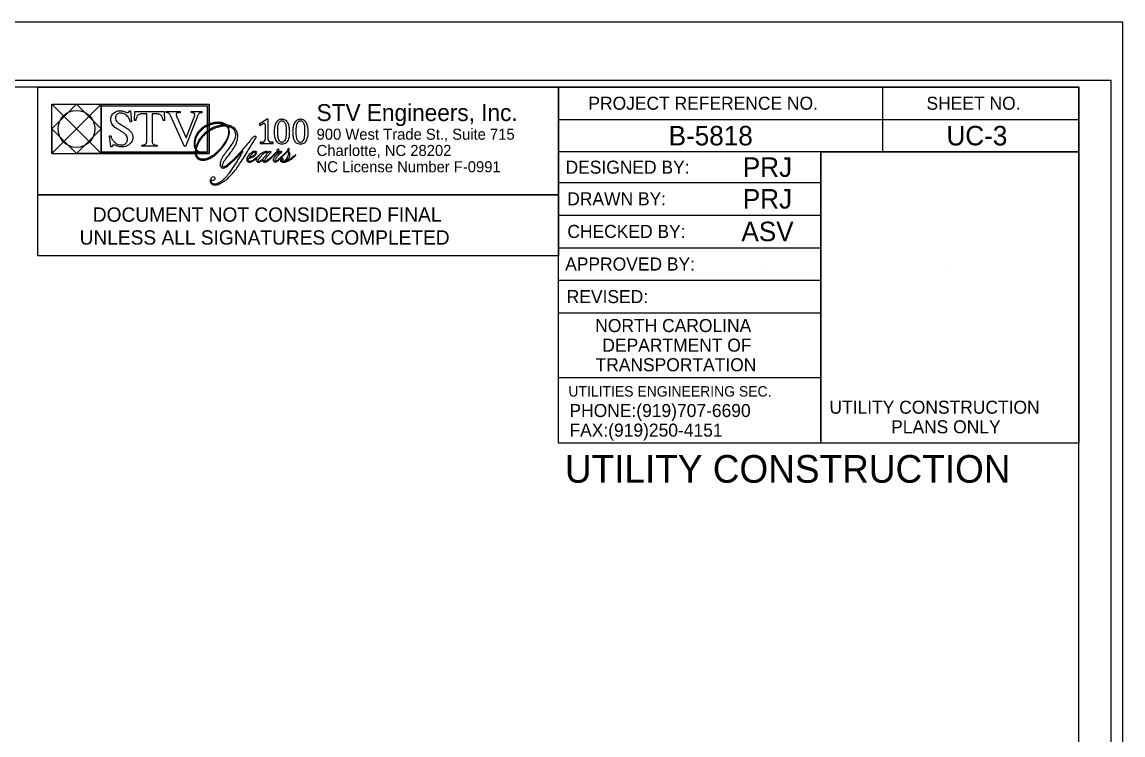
# Model space of a CAD drawing. Extents: x 0 to 674, y 0 to 440.
# Drawn here: x 504.3 to 673.6, y 330.4 to 440 of the extents above; entities that cross this region are included whole.
import ezdxf

# ---------------------------------------------------------------- set-up
doc = ezdxf.new("R2010")
doc.units = 0
for name, color, linetype in [('General Text and Text Box and Leader Line', 7, 'Continuous'), ('Old_Level_60', 7, 'Continuous'), ('Sheet Plot Border Inside CELL', 7, 'Continuous'), ('Sheet Plot Border Outside CELL', 7, 'Continuous'), ('Sheet Sticker Exception Certification CELL', 7, 'Continuous'), ('UC Notes and Details Sheet 34 CELL', 7, 'Continuous'), ('UC Plan Sheet 34 CELL', 7, 'Continuous')]:
    doc.layers.add(name, color=color, linetype=linetype)

msp = doc.modelspace()

# ---------------------------------------------------------------- linework, layer by layer
at = {"layer": 'Old_Level_60'}
for p, q in [((508.9, 427.36), (516.48, 419.78)), ((508.9, 419.78), (516.48, 427.36)), ((508.9, 423.57), (512.69, 427.36)), ((508.9, 427.36), (533.1, 427.36)), ((512.69, 427.36), (516.48, 423.57)), ((516.48, 419.78), (516.48, 427.36)), ((516.48, 427.07), (516.48, 427.36)), ((532.81, 420.07), (532.81, 427.07)), ((533.1, 419.78), (533.1, 427.36)), ((520.81, 426.34), (521, 426.34)), ((521, 426.34), (521.17, 424.64)), ((521.6, 424.88), (521.65, 426.23)), ((521.65, 426.23), (526.18, 426.23)), ((523.5, 421.64), (523.5, 425.89)), ((524.32, 425.89), (524.32, 421.64)), ((526.18, 426.23), (526.22, 424.88)), ((526.49, 426.08), (526.49, 426.23)), ((526.49, 426.23), (528.62, 426.23)), ((529.3, 420.85), (527.14, 425.65)), ((528.07, 425.51), (529.55, 422.22)), ((528.62, 426.23), (528.62, 426.07)), ((531.24, 425.4), (529.43, 420.85)), ((529.55, 422.22), (530.81, 425.39)), ((530.3, 426.08), (530.3, 426.23)), ((530.3, 426.23), (531.95, 426.23)), ((531.95, 426.23), (531.95, 426.07)), ((542.01, 425.05), (540.77, 424.29)), ((542.18, 425.05), (542.01, 425.05)), ((542.18, 421.95), (542.18, 425.05)), ((508.9, 423.57), (512.69, 419.78)), ((512.69, 419.78), (516.48, 423.57)), ((521.17, 424.64), (520.96, 424.64)), ((521.8, 424.88), (521.6, 424.88)), ((526.22, 424.88), (526.03, 424.88)), ((540.77, 424.29), (540.89, 424.09)), ((540.89, 424.09), (541.41, 424.41)), ((541.68, 424.26), (541.68, 421.95)), ((517.99, 420.83), (517.75, 422.53)), ((517.75, 422.53), (517.94, 422.53)), ((541.25, 421.52), (540.93, 421.52)), ((540.93, 421.52), (540.93, 421.31)), ((542.93, 421.52), (542.61, 421.52)), ((542.93, 421.31), (542.93, 421.52)), ((516.48, 419.78), (516.48, 420.07)), ((518.17, 420.83), (517.99, 420.83)), ((522.74, 420.93), (522.74, 421.09)), ((525.08, 420.93), (522.74, 420.93)), ((525.08, 421.09), (525.08, 420.93)), ((529.43, 420.85), (529.3, 420.85)), ((540.93, 421.31), (542.93, 421.31)), ((544.28, 421.51), (544.28, 421.51)), ((544.28, 421.28), (544.28, 421.28)), ((547.13, 421.51), (547.12, 421.51)), ((547.13, 421.28), (547.13, 421.28)), ((508.9, 419.78), (533.1, 419.78))]:
    msp.add_line(p, q, dxfattribs=at)
for points in [[(506.77, 430), (586.79, 430), (586.79, 413.45), (506.77, 413.45)], [(508.9, 423.57), (508.9, 427.36), (512.69, 427.36)], [(512.69, 427.36), (516.48, 427.36), (516.48, 423.57)], [(508.9, 423.57), (508.9, 419.78), (512.69, 419.78)], [(512.69, 419.78), (516.48, 423.57), (516.48, 419.78)]]:
    msp.add_lwpolyline(points, close=True, dxfattribs=at)
for points in [[(508.9, 419.78), (508.9, 427.36), (516.48, 427.36)], [(516.48, 427.36), (533.1, 427.36), (533.1, 419.78), (516.48, 419.78)], [(532.81, 427.07), (516.48, 427.07)], [(516.48, 420.07), (532.81, 420.07)], [(530.98, 420.43), (530.98, 420.43), (530.98, 420.43)]]:
    msp.add_lwpolyline(points, dxfattribs=at)
msp.add_circle((512.69, 423.57), 2.84, dxfattribs=at)
for centre, radius, start, end in [((541.5, 424.26), 0.178, 0, 121.5268), ((541.25, 421.95), 0.428, 270, 0), ((542.61, 421.95), 0.428, 180, 270)]:
    msp.add_arc(centre, radius, start, end, dxfattribs=at)
for points, degree in [([(517.94, 422.53), (517.98, 422.42), (518.09, 422.15), (518.31, 421.77), (518.61, 421.45), (518.93, 421.23), (519.26, 421.14), (519.58, 421.11), (519.9, 421.12), (520.17, 421.28), (520.36, 421.44), (520.46, 421.64), (520.55, 421.89), (520.55, 422.17), (520.46, 422.45), (520.23, 422.74), (519.89, 423), (519.47, 423.27), (519.12, 423.48), (518.76, 423.68), (518.46, 423.92), (518.21, 424.18), (518.03, 424.49), (517.97, 424.83), (517.96, 425.21), (518.08, 425.58), (518.26, 425.89), (518.54, 426.11), (518.79, 426.24), (519.08, 426.34), (519.39, 426.36), (519.74, 426.34), (520.05, 426.26), (520.28, 426.15), (520.46, 426.09), (520.59, 426.06), (520.71, 426.12), (520.8, 426.22), (520.81, 426.3), (520.81, 426.34)], 3), ([(520.96, 424.64), (520.94, 424.71), (520.9, 424.89), (520.79, 425.16), (520.62, 425.44), (520.4, 425.67), (520.13, 425.87), (519.88, 425.96), (519.68, 426.01), (519.48, 426.02), (519.23, 426), (518.98, 425.89), (518.79, 425.7), (518.66, 425.43), (518.66, 425.1), (518.83, 424.76), (519.13, 424.49), (519.6, 424.17), (520.18, 423.87), (520.75, 423.46), (521.17, 423.03), (521.33, 422.58), (521.36, 422.2), (521.32, 421.9), (521.21, 421.62), (521.03, 421.38), (520.81, 421.16), (520.56, 421), (520.23, 420.88), (519.76, 420.8), (519.3, 420.81), (518.97, 420.92), (518.81, 420.98), (518.65, 421.06), (518.45, 421.12), (518.26, 421.07), (518.18, 420.95), (518.17, 420.87), (518.17, 420.83)], 3), ([(523.5, 425.89), (523.32, 425.89), (523.06, 425.88), (522.74, 425.89), (522.53, 425.87), (522.32, 425.82), (522.14, 425.7), (522, 425.52), (521.9, 425.3), (521.83, 425.08), (521.81, 424.93), (521.8, 424.88)], 3), ([(526.03, 424.88), (526.02, 424.93), (525.99, 425.08), (525.93, 425.3), (525.83, 425.52), (525.69, 425.7), (525.51, 425.82), (525.3, 425.87), (525.09, 425.89), (524.76, 425.88), (524.51, 425.89), (524.32, 425.89)], 3), ([(527.14, 425.65), (527.11, 425.71), (527.03, 425.83), (526.9, 425.97), (526.75, 426.04), (526.61, 426.08), (526.53, 426.08), (526.49, 426.08)], 3), ([(528.62, 426.07), (528.55, 426.08), (528.42, 426.08), (528.24, 426.05), (528.06, 426.01), (528.02, 425.84), (528.02, 425.68), (528.05, 425.57), (528.07, 425.51)], 3), ([(530.81, 425.39), (530.83, 425.44), (530.86, 425.53), (530.89, 425.67), (530.88, 425.8), (530.83, 425.9), (530.77, 425.98), (530.65, 426.04), (530.49, 426.08), (530.37, 426.08), (530.3, 426.08)], 3), ([(531.95, 426.07), (531.93, 426.07), (531.86, 426.07), (531.77, 426.07), (531.69, 426.03), (531.59, 426), (531.51, 425.89), (531.39, 425.76), (531.32, 425.59), (531.27, 425.46), (531.24, 425.4)], 3), ([(544.28, 425.05), (544.25, 425.05), (544.15, 425.05), (543.98, 425.02), (543.77, 424.93), (543.55, 424.76), (543.35, 424.5), (543.23, 424.18), (543.14, 423.83), (543.1, 423.51), (543.09, 423.28), (543.09, 423.18)], 3), ([(545.47, 423.18), (545.47, 423.28), (545.46, 423.51), (545.42, 423.83), (545.33, 424.18), (545.21, 424.5), (545.01, 424.76), (544.8, 424.93), (544.58, 425.02), (544.42, 425.05), (544.31, 425.05), (544.28, 425.05)], 3), ([(547.13, 425.05), (547.09, 425.05), (546.99, 425.05), (546.82, 425.02), (546.61, 424.93), (546.39, 424.76), (546.2, 424.5), (546.08, 424.18), (545.98, 423.83), (545.94, 423.51), (545.94, 423.28), (545.93, 423.18)], 3), ([(548.32, 423.18), (548.31, 423.28), (548.31, 423.51), (548.27, 423.83), (548.18, 424.18), (548.06, 424.5), (547.86, 424.76), (547.64, 424.93), (547.43, 425.02), (547.26, 425.05), (547.16, 425.05), (547.13, 425.05)], 3), ([(535.79, 424.15), (535.79, 424.15), (535.69, 424.25), (535.42, 424.42), (534.96, 424.58), (534.55, 424.59), (534.12, 424.58), (533.71, 424.51), (533.17, 424.35), (532.64, 424.14), (532.14, 423.83), (531.71, 423.46), (531.23, 422.9), (530.92, 422.25), (530.78, 421.57), (530.74, 421.06), (530.86, 420.65), (530.96, 420.46), (530.98, 420.43)], 3), ([(531.03, 420.66), (530.99, 420.77), (530.92, 420.97), (530.91, 421.29), (530.94, 421.68), (531.05, 422.15), (531.27, 422.63), (531.61, 423.08), (531.98, 423.51), (532.46, 423.88), (532.98, 424.13), (533.48, 424.31), (534.03, 424.44), (534.53, 424.48), (534.93, 424.44), (535.22, 424.33), (535.41, 424.25), (535.52, 424.18), (535.54, 424.17)], 3), ([(530.98, 420.43), (530.96, 420.24), (530.95, 419.96), (530.98, 419.54), (531.14, 419.23), (531.39, 418.94), (531.73, 418.79), (532.07, 418.75), (532.43, 418.78), (532.91, 418.88), (533.49, 419.18), (534.04, 419.57), (534.56, 420.07), (535.1, 420.65), (535.57, 421.31), (535.89, 421.88), (536.08, 422.33), (536.19, 422.74), (536.22, 423.18), (536.16, 423.6), (536.03, 423.86), (535.95, 423.98)], 3), ([(535.54, 424.17), (535.53, 424.17), (535.24, 424.18), (534.74, 424.13), (533.98, 423.91), (533.25, 423.58), (532.66, 423.13), (532.12, 422.62), (531.59, 422.04), (531.23, 421.32), (531.07, 420.84), (531.03, 420.66)], 3), ([(535.72, 424.02), (535.72, 424.01), (535.77, 423.96), (535.92, 423.79), (536.06, 423.46), (536.11, 423.02), (536.02, 422.54), (535.8, 421.96), (535.44, 421.33), (534.97, 420.69), (534.51, 420.21), (534.12, 419.85), (533.76, 419.55), (533.37, 419.31), (532.98, 419.1), (532.63, 418.98), (532.3, 418.9), (531.99, 418.9), (531.72, 418.95), (531.48, 419.11), (531.26, 419.29), (531.12, 419.58), (531.06, 419.91), (531.07, 420.15), (531.09, 420.28)], 3), ([(531.12, 420.45), (531.13, 420.46), (531.15, 420.55), (531.24, 420.83), (531.36, 421.24), (531.64, 421.72), (531.92, 422.17), (532.26, 422.55), (532.62, 422.89), (532.96, 423.19), (533.4, 423.43), (533.9, 423.69), (534.46, 423.89), (535.07, 424.01), (535.48, 424.05), (535.7, 424.02), (535.72, 424.02)], 3), ([(538.25, 420.16), (538.15, 419.97), (537.82, 419.33), (537.23, 418.38), (536.58, 417.36), (535.97, 416.51), (535.43, 415.92), (534.95, 415.49), (534.58, 415.26), (534.25, 415.1), (533.94, 415.08), (533.68, 415.12), (533.49, 415.27), (533.4, 415.45), (533.41, 415.59), (533.49, 415.68), (533.62, 415.69), (533.78, 415.7), (533.99, 415.77), (534.05, 416.01), (533.88, 416.2), (533.61, 416.19), (533.41, 416.01), (533.24, 415.78), (533.26, 415.49), (533.34, 415.23), (533.53, 415.04), (533.82, 414.95), (534.12, 414.96), (534.45, 415.03), (534.85, 415.19), (535.28, 415.46), (535.79, 415.82), (536.37, 416.38), (536.95, 417.02), (537.51, 417.79), (538.04, 418.59), (538.69, 419.61), (539.26, 420.56), (539.74, 421.36), (540.05, 421.8), (540.22, 422.1), (540.32, 422.25), (540.34, 422.43), (540.16, 422.41), (540.02, 422.4), (539.85, 422.3), (539.67, 422.12), (539.42, 421.78), (538.98, 421.25), (538.31, 420.48), (537.51, 419.55), (536.65, 418.69), (536, 418.09), (535.57, 417.82), (535.37, 417.71), (535.16, 417.7), (535.1, 417.89), (535.15, 418.11), (535.33, 418.54), (535.65, 418.96), (536.09, 419.52), (536.56, 420.14), (537.11, 420.96), (537.49, 421.9), (537.52, 422.85), (537.16, 423.56), (536.64, 423.96), (536.18, 424.1), (535.9, 424.14), (535.79, 424.15)], 3), ([(535.95, 423.98), (535.95, 423.98), (536.02, 423.96), (536.14, 423.94), (536.37, 423.87), (536.61, 423.73), (536.85, 423.53), (536.99, 423.29), (537.11, 423.04), (537.15, 422.72), (537.13, 422.3), (536.95, 421.83), (536.63, 421.31), (536.25, 420.76), (535.68, 420), (535.1, 419.24), (534.79, 418.45), (534.77, 417.97), (534.87, 417.7), (535.06, 417.56), (535.23, 417.55), (535.47, 417.59), (535.73, 417.75), (536.05, 417.97), (536.48, 418.36), (537.01, 418.85), (537.63, 419.51), (538.03, 419.93), (538.25, 420.16)], 3), ([(543.63, 423.18), (543.64, 423.33), (543.65, 423.62), (543.66, 424.03), (543.75, 424.36), (543.86, 424.58), (543.98, 424.71), (544.1, 424.79), (544.18, 424.81), (544.25, 424.82), (544.28, 424.82)], 3), ([(544.28, 424.82), (544.32, 424.82), (544.38, 424.81), (544.47, 424.79), (544.58, 424.71), (544.7, 424.58), (544.82, 424.36), (544.9, 424.03), (544.92, 423.62), (544.92, 423.33), (544.93, 423.18)], 3), ([(546.48, 423.18), (546.48, 423.33), (546.49, 423.62), (546.51, 424.03), (546.59, 424.36), (546.71, 424.58), (546.82, 424.71), (546.94, 424.79), (547.03, 424.81), (547.09, 424.82), (547.13, 424.82)], 3), ([(547.13, 424.82), (547.16, 424.82), (547.22, 424.81), (547.31, 424.79), (547.43, 424.71), (547.54, 424.58), (547.66, 424.36), (547.75, 424.03), (547.76, 423.62), (547.77, 423.33), (547.77, 423.18)], 3), ([(522.74, 421.09), (522.78, 421.09), (522.89, 421.09), (523.07, 421.1), (523.24, 421.17), (523.39, 421.25), (523.45, 421.38), (523.5, 421.54), (523.5, 421.66), (523.5, 421.73)], 3), ([(524.32, 421.73), (524.32, 421.66), (524.32, 421.54), (524.37, 421.38), (524.43, 421.25), (524.58, 421.17), (524.76, 421.1), (524.93, 421.09), (525.04, 421.09), (525.08, 421.09)], 3), ([(543.09, 423.18), (543.09, 423.11), (543.1, 422.91), (543.1, 422.59), (543.17, 422.24), (543.27, 421.91), (543.43, 421.64), (543.62, 421.44), (543.9, 421.29), (544.13, 421.29), (544.28, 421.28)], 3), ([(544.28, 421.51), (544.23, 421.51), (544.11, 421.52), (543.94, 421.65), (543.8, 421.87), (543.7, 422.16), (543.66, 422.52), (543.63, 422.86), (543.63, 423.08), (543.63, 423.18)], 3), ([(544.28, 421.28), (544.44, 421.29), (544.67, 421.29), (544.95, 421.44), (545.14, 421.64), (545.29, 421.91), (545.39, 422.24), (545.46, 422.59), (545.46, 422.91), (545.47, 423.11), (545.47, 423.18)], 3), ([(544.93, 423.18), (544.93, 423.08), (544.94, 422.86), (544.9, 422.52), (544.87, 422.16), (544.76, 421.87), (544.62, 421.65), (544.46, 421.52), (544.33, 421.51), (544.28, 421.51)], 3), ([(545.93, 423.18), (545.94, 423.11), (545.94, 422.91), (545.95, 422.59), (546.02, 422.24), (546.11, 421.91), (546.27, 421.64), (546.46, 421.44), (546.74, 421.29), (546.97, 421.29), (547.13, 421.28)], 3), ([(547.12, 421.51), (547.07, 421.51), (546.95, 421.52), (546.79, 421.65), (546.64, 421.87), (546.54, 422.16), (546.51, 422.52), (546.47, 422.86), (546.48, 423.08), (546.48, 423.18)], 3), ([(547.13, 421.28), (547.28, 421.29), (547.51, 421.29), (547.79, 421.44), (547.98, 421.64), (548.14, 421.91), (548.23, 422.24), (548.3, 422.59), (548.31, 422.91), (548.31, 423.11), (548.32, 423.18)], 3), ([(547.77, 423.18), (547.77, 423.08), (547.78, 422.86), (547.74, 422.52), (547.71, 422.16), (547.61, 421.87), (547.47, 421.65), (547.3, 421.52), (547.18, 421.51), (547.13, 421.51)], 3), ([(530.98, 420.43), (530.98, 420.43), (530.98, 420.43), (530.98, 420.43)], 2), ([(531.09, 420.28), (531.1, 420.27), (531.16, 420.18), (531.26, 420.07), (531.41, 419.99), (531.49, 419.97), (531.52, 419.96)], 3), ([(531.52, 419.96), (531.52, 419.96), (531.54, 419.96), (531.57, 419.98), (531.56, 420.01), (531.55, 420.03), (531.49, 420.09), (531.32, 420.18), (531.19, 420.34), (531.13, 420.45), (531.12, 420.45)], 3), ([(542.14, 419.91), (542.13, 420), (542.09, 420.08), (541.89, 420.09), (541.63, 420.08), (541.35, 419.95), (541.12, 419.81), (540.87, 419.64), (540.65, 419.42), (540.43, 419.19), (540.1, 418.95), (539.99, 418.87), (539.79, 418.73), (539.57, 418.65), (539.39, 418.57), (539.25, 418.58), (539.14, 418.63), (539.08, 418.74), (539.08, 418.88), (539.14, 418.97), (539.18, 419.07), (539.31, 419.08), (539.49, 419.14), (539.71, 419.22), (539.94, 419.36), (540.17, 419.51), (540.35, 419.72), (540.44, 419.96), (540.3, 420.12), (540.15, 420.11), (539.94, 420.1), (539.68, 419.97), (539.38, 419.78), (539.12, 419.48), (538.9, 419.22), (538.85, 418.95), (538.86, 418.77), (538.94, 418.61), (539.07, 418.52), (539.22, 418.46), (539.41, 418.46), (539.66, 418.55), (539.92, 418.72), (540.21, 418.9), (540.36, 419.04), (540.43, 419.11)], 3), ([(539.26, 419.17), (539.31, 419.24), (539.4, 419.38), (539.57, 419.62), (539.75, 419.82), (539.95, 419.95), (540.06, 420.03), (540.16, 420.05), (540.23, 420.02), (540.28, 419.94), (540.22, 419.8), (540.12, 419.66), (539.96, 419.51), (539.77, 419.37), (539.58, 419.29), (539.4, 419.22), (539.31, 419.19), (539.26, 419.17)], 3), ([(541.33, 418.98), (541.26, 418.92), (541.09, 418.77), (540.89, 418.59), (540.69, 418.54), (540.59, 418.59), (540.59, 418.74), (540.68, 418.95), (540.95, 419.28), (541.25, 419.6), (541.52, 419.83), (541.68, 419.93), (541.81, 419.97), (541.94, 419.99), (542.08, 419.86), (541.91, 419.61), (541.72, 419.39), (541.51, 419.16), (541.38, 419.03), (541.33, 418.98)], 3), ([(541.36, 418.88), (541.35, 418.84), (541.33, 418.76), (541.32, 418.62), (541.41, 418.47), (541.59, 418.46), (541.84, 418.49), (542.13, 418.71), (542.47, 418.95), (542.74, 419.22), (542.99, 419.45), (543.24, 419.71), (543.42, 419.9), (543.52, 420.01)], 3), ([(544.69, 418.57), (544.73, 418.59), (544.86, 418.66), (545.07, 418.81), (545.28, 418.99), (545.44, 419.22), (545.52, 419.47), (545.52, 419.74), (545.44, 419.94), (545.34, 420.06), (545.31, 420.14), (545.26, 420.18), (545.28, 420.24), (545.35, 420.26), (545.39, 420.35), (545.41, 420.44), (545.38, 420.55), (545.26, 420.56), (545.19, 420.48), (545.13, 420.37), (545.16, 420.22), (545, 420.1), (544.83, 419.9), (544.52, 419.6), (544.22, 419.29), (543.94, 419.05), (543.77, 418.9), (543.64, 418.78), (543.5, 418.69), (543.39, 418.62), (543.25, 418.59), (543.21, 418.73), (543.24, 418.83), (543.32, 418.99), (543.45, 419.17), (543.61, 419.39), (543.78, 419.57), (543.96, 419.74), (544.1, 419.9), (544.23, 419.98), (544.28, 420.06), (544.21, 420.15), (544.1, 420.09), (543.98, 420.05), (543.86, 420.06), (543.65, 420.06), (543.71, 420.12), (543.75, 420.16), (543.84, 420.23), (543.84, 420.38), (543.74, 420.47), (543.62, 420.45), (543.54, 420.36), (543.49, 420.25), (543.51, 420.16), (543.46, 420.03), (543.3, 419.89), (543.05, 419.64), (542.77, 419.35), (542.4, 419.04), (542.1, 418.79), (541.86, 418.64), (541.73, 418.58), (541.64, 418.57), (541.58, 418.61), (541.58, 418.68), (541.61, 418.75), (541.7, 418.89), (541.84, 419.1), (542.12, 419.42), (542.39, 419.75), (542.56, 419.98), (542.62, 420.06)], 3), ([(542.26, 420.06), (542.22, 420.01), (542.18, 419.96), (542.14, 419.91)], 2), ([(542.62, 420.06), (542.5, 420.06), (542.38, 420.06), (542.26, 420.06)], 2), ([(543.89, 419.93), (543.8, 419.87), (543.62, 419.73), (543.41, 419.51), (543.22, 419.32), (543.08, 419.16), (542.98, 418.99), (542.93, 418.82), (542.93, 418.62), (543.1, 418.47), (543.31, 418.49), (543.51, 418.57), (543.74, 418.76), (544.05, 419), (544.52, 419.49), (544.9, 419.87), (545.16, 420.13)], 3), ([(543.52, 420.01), (543.55, 419.99), (543.63, 419.94), (543.76, 419.93), (543.85, 419.93), (543.89, 419.93)], 3), ([(545.16, 420.13), (545.19, 420.11), (545.26, 420.03), (545.27, 419.82), (545.26, 419.57), (545.14, 419.28), (544.97, 418.98), (544.75, 418.75), (544.56, 418.61), (544.41, 418.55), (544.28, 418.56), (544.19, 418.62), (544.15, 418.69), (544.18, 418.77), (544.23, 418.82), (544.31, 418.81), (544.39, 418.8), (544.46, 418.87), (544.5, 418.97), (544.39, 419.05), (544.25, 419.05), (544.12, 418.95), (544.05, 418.81), (544.04, 418.64), (544.17, 418.5), (544.41, 418.46), (544.7, 418.45), (545.02, 418.56), (545.36, 418.7), (545.68, 418.91), (546.03, 419.16), (546.26, 419.38), (546.42, 419.51), (546.44, 419.61), (546.36, 419.6), (546.27, 419.51), (546.13, 419.37), (545.88, 419.18), (545.62, 418.97), (545.33, 418.8), (545.08, 418.67), (544.87, 418.57), (544.74, 418.57), (544.69, 418.57)], 3), ([(540.43, 419.11), (540.4, 419.06), (540.36, 418.97), (540.33, 418.82), (540.35, 418.65), (540.47, 418.51), (540.64, 418.45), (540.81, 418.47), (540.98, 418.55), (541.12, 418.66), (541.24, 418.78), (541.32, 418.85), (541.36, 418.88)], 3)]:
    msp.add_open_spline(points, degree=degree, dxfattribs=at)
at = {"layer": 'Sheet Plot Border Inside CELL'}
msp.add_lwpolyline([(671.8, 431.01), (5.2, 431.01), (5.2, 8.97), (671.8, 8.97)], close=True, dxfattribs=at)
at = {"layer": 'Sheet Plot Border Outside CELL'}
msp.add_lwpolyline([(673.6, 440), (0, 440), (0, 0), (673.6, 0)], close=True, dxfattribs=at)
at = {"layer": 'Sheet Sticker Exception Certification CELL'}
for p, q in [((506.77, 404.05), (506.77, 413.45)), ((506.77, 413.45), (586.79, 413.45)), ((586.79, 413.45), (586.79, 404.05)), ((586.79, 404.05), (506.77, 404.05))]:
    msp.add_line(p, q, dxfattribs=at)
at = {"layer": 'UC Notes and Details Sheet 34 CELL'}
for p, q in [((611.7, 422.54), (611.7, 422.54)), ((651.71, 422.54), (651.71, 422.54)), ((618.9, 417.7), (618.9, 417.7)), ((586.79, 415.34), (627.16, 415.34)), ((618.9, 412.83), (618.9, 412.83)), ((586.79, 410.33), (627.16, 410.33)), ((618.9, 407.82), (618.9, 407.82)), ((586.79, 405.32), (627.16, 405.32)), ((618.9, 402.81), (618.9, 402.81)), ((647.29, 401.75), (647.29, 401.75)), ((586.79, 400.31), (627.16, 400.31)), ((586.79, 395.29), (627.16, 395.29)), ((586.79, 385.35), (627.16, 385.35))]:
    msp.add_line(p, q, dxfattribs=at)
msp.add_lwpolyline([(666.8, 430), (66.8, 430), (66.8, 10), (666.8, 10)], close=True, dxfattribs=at)
for points in [[(586.79, 430), (666.8, 430), (666.8, 420.05)], [(666.8, 420.05), (586.79, 420.05), (586.79, 430)], [(627.16, 420.05), (627.16, 375.27), (586.79, 375.27), (586.79, 430)], [(666.8, 375.27), (627.16, 375.27), (627.16, 420.05), (666.8, 420.05)], [(666.8, 420.05), (666.8, 375.27)]]:
    msp.add_lwpolyline(points, dxfattribs=at)
at = {"layer": 'UC Plan Sheet 34 CELL'}
for p, q in [((636.62, 430), (636.62, 420.05)), ((586.79, 425.04), (666.8, 425.04))]:
    msp.add_line(p, q, dxfattribs=at)

# ---------------------------------------------------------------- texts
at = {"layer": 'General Text and Text Box and Leader Line'}
for s, p in [('B-5818', (603.74, 421.04)), ('UC-3', (646.46, 421.04)), ('PRJ', (615.15, 416.2)), ('PRJ', (615.15, 411.33)), ('ASV', (614.93, 406.32))]:
    msp.add_text(s, height=3, rotation=360, dxfattribs=at).set_placement(p)
at = {"layer": 'Old_Level_60'}
msp.add_text('STV Engineers, Inc.', height=2.6, dxfattribs=at).set_placement((549.61, 424.78))
for s, p in [('900 West Trade St., Suite 715', (549.61, 421.91)), ('Charlotte, NC 28202', (549.61, 419.41)), ('NC License Number F-0991', (549.61, 416.91))]:
    msp.add_text(s, height=1.7, rotation=360, dxfattribs=at).set_placement(p)
at = {"layer": 'Sheet Sticker Exception Certification CELL'}
for s, p in [('DOCUMENT NOT CONSIDERED FINAL', (515.2, 409.31)), ('UNLESS ALL SIGNATURES COMPLETED', (513.17, 405.79))]:
    msp.add_text(s, height=2.2, rotation=360, dxfattribs=at).set_placement(p)
at = {"layer": 'UC Notes and Details Sheet 34 CELL'}
for s, height, p in [('PROJECT REFERENCE NO.', 2.0046, (591.4, 426.52)), ('SHEET NO.', 2.005, (643.39, 426.52)), ('DESIGNED BY:', 2.0046, (587.89, 416.69)), ('DRAWN BY:', 2.005, (588.15, 411.83)), ('CHECKED BY:', 2.0046, (588.17, 406.82)), ('APPROVED BY:', 2.0046, (587.83, 401.81)), ('REVISED:', 2.005, (588.07, 396.8)), ('NORTH CAROLINA', 2.0046, (592.46, 392.35)), ('DEPARTMENT OF', 2.0046, (593.55, 389.34)), ('TRANSPORTATION', 2.0046, (592.5, 386.33)), ('UTILITIES ENGINEERING SEC.', 1.6037, (588.33, 382.44)), ('PHONE:(919)707-6690', 2.0046, (588.49, 379.29)), ('UTILITY CONSTRUCTION', 2.0046, (628.47, 379.8)), ('FAX:(919)250-4151', 2.0046, (588.49, 376.28)), ('PLANS ONLY', 2.005, (637.95, 376.79)), ('UTILITY CONSTRUCTION', 4.25, (587.79, 369.2))]:
    msp.add_text(s, height=height, rotation=360, dxfattribs=at).set_placement(p)

doc.saveas('drawing.dxf')
